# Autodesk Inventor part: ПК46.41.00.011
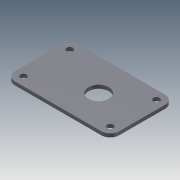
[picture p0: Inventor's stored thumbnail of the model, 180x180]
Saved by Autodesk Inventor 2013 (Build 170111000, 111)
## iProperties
Created: 2005-05
Part Number: ПК46.41.00.011
Material: Steel, Mild
Document SubType Name: Листовой материал
Designer: PVitaliy
Manufacturer: Standard
Standards Organization: Custom
Description: Плита
Density: 7.86 g/cm^3
Sheet Metal Rule: По умолчанию
Author: PVitaliy
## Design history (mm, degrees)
node "Грань1"
  sketch "Эскиз2"
    geometry: L1 (15, 0)-(165, 0); L2 (180, 15)-(180, 95); L3 (165, 110)-(15, 110); L4 (0, 95)-(0, 15); L5 (15, 95)-(165, 95); L6 (165, 95)-(165, 15); L7 (165, 15)-(15, 15); L8 (15, 15)-(15, 95); C1 r 5.5 at (15, 95); C2 r 5.5 at (15, 15); C3 r 5.5 at (165, 95); C4 r 5.5 at (165, 15); A1 r 15 centre (15, 95) between (15, 110) and (0, 95); A2 r 15 centre (15, 15) between (0, 15) and (15, 0); A3 r 15 centre (165, 15) between (165, 0) and (180, 15); A4 r 15 centre (165, 95) between (180, 95) and (165, 110)
    constraints: 16 end point, 8 centre point, 8 point on circle, 7 coincident, 4 parallel, 4 tangent, 3 equal radius, 2 horizontal, 2 perpendicular
    dimensions: "d0" = 150 distance of L5.start L5.end; "d1" = 80 distance of L5.end L6.end; "d2" = 15 distance between parallel lines of L8 L4; "d3" = 15 distance between parallel lines of L2 L6; "d4" = 15 distance between parallel lines of L1 L7; "d5" = 15 distance between parallel lines of L5 L3; "d6" = 11 diameter of C1
node "РабПлоскость1"
hole "Отверстие2" diameter "d19" = 35; stored, may be unused: countersink angle "d23" = 90 deg, drill point angle "d25" = 118 deg; dims "d17" = 75, "d18" = 55, "d20" = 6, "d21" = 4, "d22" = 2, "d24" = 6 (= Толщина)
body "Solid1"
feature "Плакирование1" dims "Толщина" = 6
other parameters: "Радиус_гибки" = 6 (= Толщина), "Ширина_просечки" = 6 (= Толщина), "Глубина_просечки" = 3 (= 0.5 x Толщина), "Размер_высечки" = 24 (= 4 x Толщина), "Зазор_стыка" = 0.01, "Минимальный_остаток" = 12 (= 2 x Толщина), "Радиус_перехода" = 6 (= Радиус_гибки), "d7" = 6 (= Радиус_гибки), "JacobiRadiusSize" = 6 (= Толщина), "GapSize" = 6 (= Толщина)
